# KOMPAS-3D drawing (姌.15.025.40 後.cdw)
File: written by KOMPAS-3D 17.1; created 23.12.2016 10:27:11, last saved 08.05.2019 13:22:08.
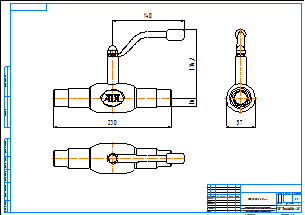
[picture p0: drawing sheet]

Sheet 1: A2, landscape

Title block, sheet 1: name: КШ.15.025.40 сс; material: Внимание! Данный продукт является объектом авторского права ООО «Торговый Дом АДЛ». / Запрещается изменение, копирование, распространение / (в том числе путем копирования на другие сайты и ресурсы в Интернете) / или любое иное использование информации и объектов без предварительного / согласия правообладателя (ООО «Торговый Дом АДЛ»).; sheets: 1; organisation: ООО "Торговый дом АДЛ"; sheet format: A2; stored path: C:\Users\tra\Desktop\2д чертежи\Шаровые краны БИВАЛ\КШ_Бивал_серия_14_15\KOMPAS_2D\КШ.15.025.40 сс.cdw

Views: Вид 1, Проекционный вид 2, Проекционный вид 3
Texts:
  Klimkovich
  ADL
Dimensions and other numbers on the sheet: 230; 140; 134,2; 16; 57; 1:1; 1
